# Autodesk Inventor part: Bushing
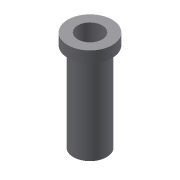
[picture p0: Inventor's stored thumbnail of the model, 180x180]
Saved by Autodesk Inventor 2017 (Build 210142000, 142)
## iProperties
Shininess: 77.0
Length Units: 11269
Angle Units: 11279
Time Units: 11290
Mass Units: 11283
Length Display Precision: 3
Angle Display Precision: 2
Created: 2002-02
Part Number: Bushing
Document SubType Name: Modeling
Designer: ***
Density: 1 g/cm^3
Material: Generic
Appearance: Default
Density: 0.0
Volumn: 0.0
Area: 0.0
PropertySet Name: Model Information
Control State: 0
Master: False
Checked Out: False
Author: ***
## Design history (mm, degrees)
sketch "Sketch2"
  geometry: C1 r 10 at (0, 0); 1 further point
  constraints: 1 centre point, 1 coincident
  dimensions: "d8" = 20 diameter of C1
extrude "Extrusion1" new body sketch "Sketch2" distance "d6" = 5; taper "d7" = 0 deg
sketch "Sketch4"
  geometry: C1 r 7.5 at (0, 0); 1 further point
  constraints: 1 centre point, 1 coincident
  dimensions: "d9" = 15 diameter of C1
extrude "Extrusion2" join sketch "Sketch4" distance "d10" = 40; taper "d11" = 0 deg
sketch "Sketch5"
  geometry: C1 r 5.5 at (0, 0); 1 further point
  constraints: 1 centre point, 1 coincident
  dimensions: "d12" = 11 diameter of C1
extrude "Extrusion3" cut sketch "Sketch5" distance "d13" = 57.75; taper "d14" = 0 deg
body "Solid2"
